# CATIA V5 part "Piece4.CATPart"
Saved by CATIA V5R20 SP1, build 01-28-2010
Part number: Piece4
Bounding box of the stored display mesh (mm): x -4 to 0, y 40.884 to 67.753, z -80.108 to 26.965
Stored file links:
  F:\TRAV\IAO\Exercice IAO\Catia\Piece4.CATPart
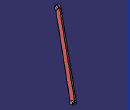
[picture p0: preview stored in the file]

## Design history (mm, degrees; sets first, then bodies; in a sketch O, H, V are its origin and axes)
Body1 (main body)
  Plane1: stored without definition
  Point1 "H": stored without definition
  Point2 "G": stored without definition
  Point3 "H": stored without definition
  Sketch1 on Plane1, origin (-2, 0, 0), H (0, 1, 0), V (0, 0, 1)
    line L1 (67.6909, -76.2917) -> (46.8188, 24.5758)
    arc A1 centre (43.881, 23.9679) radius 3 from (46.8188, 24.5758) to (40.9412, 23.37) ccw
    point P3 (43.881, 23.9679)
    line L2 (40.9412, 23.37) -> (61.4682, -77.5682)
    arc A2 centre (64.5806, -76.9353) radius 3.1761 from (61.4682, -77.5682) to (67.6909, -76.2917) ccw
    point P6 (64.5806, -76.9353)
    reference projected point E1 (43.881, 23.9679) from Point2
    reference projected point E2 (64.5806, -76.9353) from Point3
    radius A1 = 3
    tangency: A1 L1, L2 A1, A2 L1, A2 L2
    coincidence: E1 P3, E2 P6
  Pad1: profile Sketch1, direction (-1, 0, 0), length 2
  Point4 "G": stored without definition
  DatumCurve1
  Point5 "H": stored without definition
  Point6 "H": stored without definition
  Sketch2 on start face of Pad1, origin (-2, 0, 0), H (0, 1, 0), V (0, 0, 1)
    circle A1 centre (43.881, 23.9679) radius 1.8692
    point P1 (43.881, 23.9679)
    reference projected point E1 (43.881, 23.9679) from Point4
    reference projected circle E2 centre (43.881, 23.9679) radius 1.8692 from edge of DatumCurve1
    circle A2 centre (64.5806, -76.9353) radius 2
    point P2 (64.5806, -76.9353)
    reference projected point E3 (64.5806, -76.9353) from Point6
    radius A2 = 2
    coincidence: E1 P1, A1 E2, E3 P2
  Pad2: profile Sketch2, direction (1, 0, 0), length 2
